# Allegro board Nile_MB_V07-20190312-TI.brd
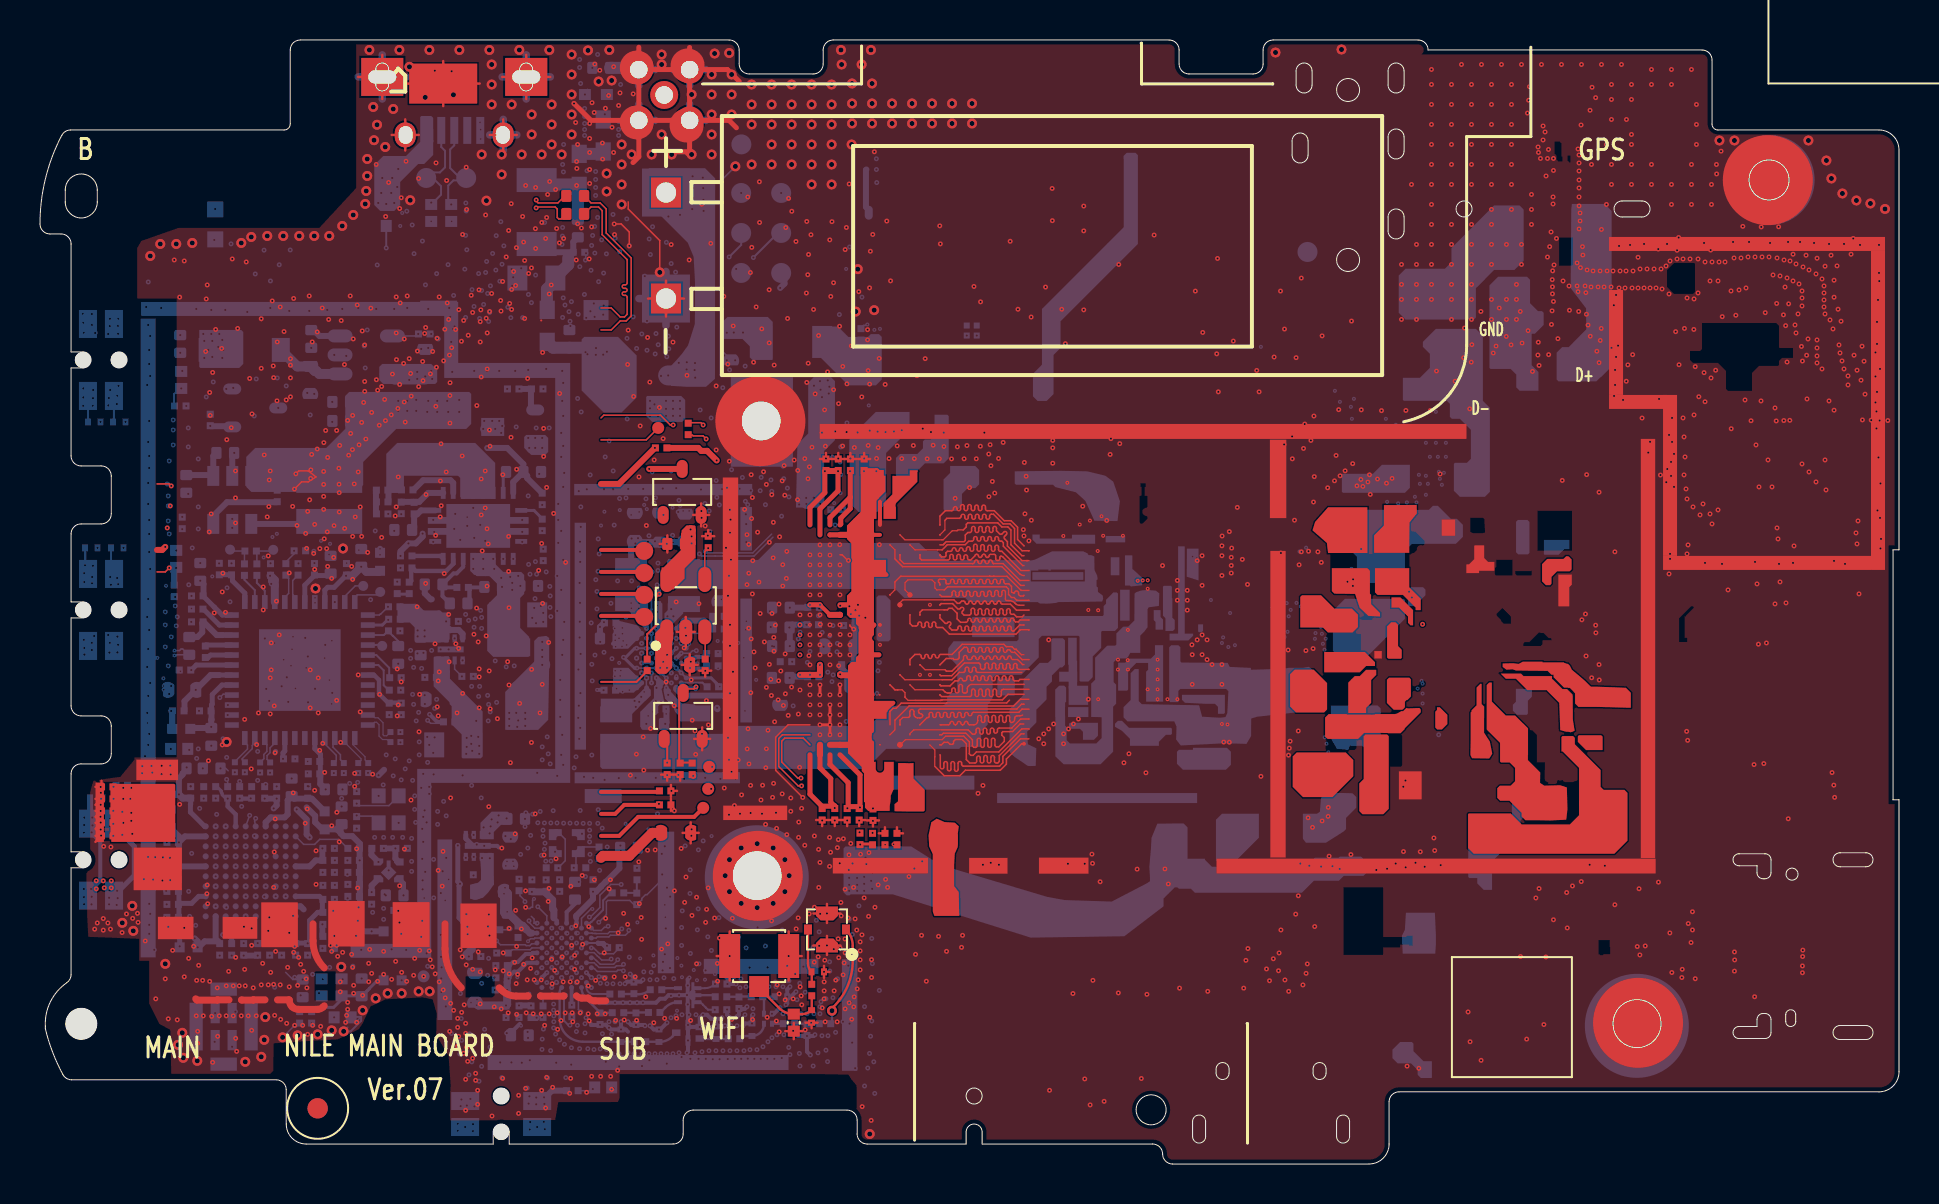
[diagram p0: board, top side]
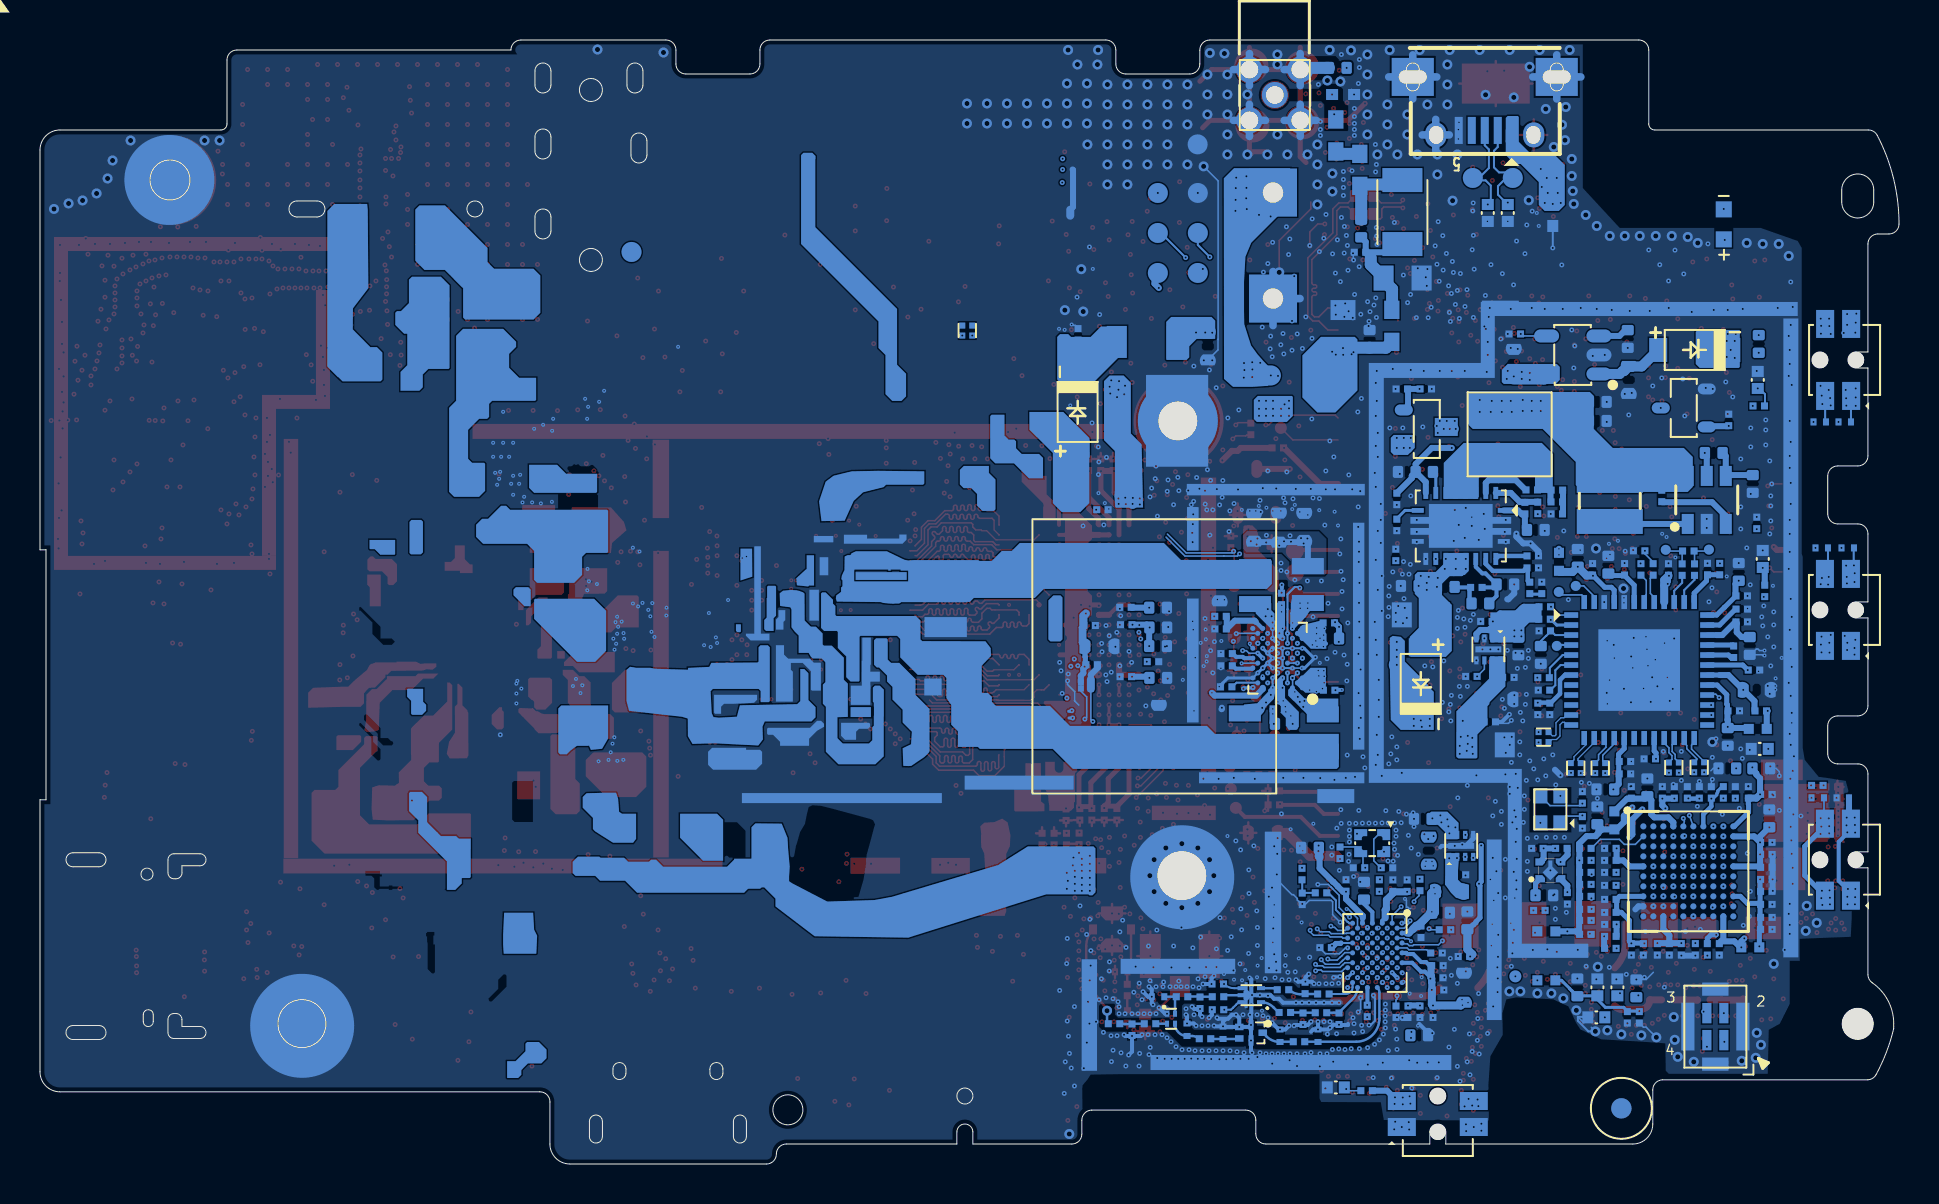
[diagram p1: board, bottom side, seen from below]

Outline 92.96 x 56.21 mm; copper layers: TOP, INNER LAYER 2, INNER LAYER 3, INNER LAYER 4, INNER LAYER 5, INNER LAYER 6, INNER LAYER 7, INNER LAYER 8, INNER LAYER 9, BOTTOM. Coordinates in mm from the lower left corner of the outline.

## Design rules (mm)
net group DIFFPAIR4: nets USB3_HS_CONN_DM_R USB3_HS_CONN_DP_R
net group DIFFPAIR5: nets USB3_HS_DET_DM USB3_HS_DET_DP
net group DIFFPAIR6: nets MIPI_DSI0_L0_M MIPI_DSI0_L0_P
net group DIFFPAIR7: nets MIPI_DSI0_CLK_M MIPI_DSI0_CLK_P
net group DIFFPAIR8: nets MIPI_DSI0_L1_M MIPI_DSI0_L1_P
net group DIFFPAIR18: nets USB_HUB2_DN USB_HUB2_DP
net group DIFFPAIR19: nets RIN0_M RIN0_P
net group DIFFPAIR20: nets N17038564 N17038587
net group DIFFPAIR21: nets N13800591 N13800619
net group DP_AUX: nets DP_AUX_M DP_AUX_P
net group EBI1EBI0_CLK_: nets EBI0_CLK_N EBI0_CLK_P
net group EBI1EBI0_DQS_0_: nets EBI0_DQS_0_N EBI0_DQS_0_P
net group EBI1EBI0_DQS_1_: nets EBI0_DQS_1_N EBI0_DQS_1_P
net group EBI1EBI1_CLK_: nets EBI1_CLK_N EBI1_CLK_P
net group EBI1EBI1_DQS_0_: nets EBI1_DQS_0_N EBI1_DQS_0_P
net group EBI1EBI1_DQS_1_: nets EBI1_DQS_1_N EBI1_DQS_1_P
net group IMP: nets CAM_MCLK0 SLEEP_CLK
net group IMP_50_OHM: nets SPMI_CLK SPMI_DATA
net group MIPI_CSI0_CLK_M: nets MIPI_CSI0_CLK_M MIPI_CSI0_CLK_M_R
net group MIPI_CSI0_CLK_P: nets MIPI_CSI0_CLK_P MIPI_CSI0_CLK_P_R
net group MIPI_CSI0_L0_DATA_M: nets MIPI_CSI0_L0_DATA_M MIPI_CSI0_L0_DATA_M_R
net group MIPI_CSI0_L0_DATA_P: nets MIPI_CSI0_L0_DATA_P MIPI_CSI0_L0_DATA_P_R
net group MIPI_CSI0_L1_DATA_M: nets MIPI_CSI0_L1_DATA_M MIPI_CSI0_L1_DATA_M_R
net group MIPI_CSI0_L1_DATA_P: nets MIPI_CSI0_L1_DATA_P MIPI_CSI0_L1_DATA_P_R
net group MIPI_CSI0_L2_DATA_M: nets MIPI_CSI0_L2_DATA_M MIPI_CSI0_L2_DATA_M_R
net group MIPI_CSI0_L2_DATA_P: nets MIPI_CSI0_L2_DATA_P MIPI_CSI0_L2_DATA_P_R
net group MIPI_CSI0_L3_DATA_M: nets MIPI_CSI0_L3_DATA_M MIPI_CSI0_L3_DATA_M_R
net group MIPI_CSI0_L3_DATA_P: nets MIPI_CSI0_L3_DATA_P MIPI_CSI0_L3_DATA_P_R
net group MIPI_CSI1_CLK: nets MIPI_CSI1_CLK_M MIPI_CSI1_CLK_P
net group MIPI_CSI1_L0: nets MIPI_CSI1_L0_DATA_M MIPI_CSI1_L0_DATA_P
net group MIPI_CSI1_L1: nets MIPI_CSI1_L1_DATA_M MIPI_CSI1_L1_DATA_P
net group MIPI_CSI1_L2: nets MIPI_CSI1_L2_DATA_M MIPI_CSI1_L2_DATA_P
net group MIPI_CSI1_L3: nets MIPI_CSI1_L3_DATA_M MIPI_CSI1_L3_DATA_P
net group SDC1_CLK: nets N16803139 SDC1_CLK
net group SDC1_RCLK: nets N16802968 SDC1_RCLK
net group SDC2_CLK: nets N13685743 SDC2_CLK
net group USB2_HS_D: nets USB2_HS_D_M USB2_HS_D_P
net group USB3_SBU: nets USB3_SBU1 USB3_SBU2
net group USB3_SS_RX0_CONN_M: nets USB3_SS_RX0_CONN_M USB3_SS_RX0_N
net group USB3_SS_RX0_CONN_P: nets USB3_SS_RX0_CONN_P USB3_SS_RX0_P
net group USB3_SS_RX1_CONN_M: nets USB3_SS_RX1_CONN_M USB3_SS_RX1_N
net group USB3_SS_RX1_CONN_P: nets USB3_SS_RX1_CONN_P USB3_SS_RX1_P
net group USB3_SS_TX0_CONN_M: nets USB3_SS_TX0_CONN_M USB3_SS_TX0_N
net group USB3_SS_TX0_CONN_P: nets USB3_SS_TX0_CONN_P USB3_SS_TX0_P
net group USB3_SS_TX1_CONN_M: nets USB3_SS_TX1_CONN_M USB3_SS_TX1_N
net group USB3_SS_TX1_CONN_P: nets USB3_SS_TX1_CONN_P USB3_SS_TX1_P
net group USB_HUB1: nets USB_HUB1_DN USB_HUB1_DP
net group DDR_EBI0_DQ0-7: nets EBI0_DQ0 EBI0_DQ1 EBI0_DQ2 EBI0_DQ3 EBI0_DQ4 EBI0_DQ5 EBI0_DQ6 EBI0_DQ7
net group DDR_EBI0_DQ8-15: nets EBI0_DQ8 EBI0_DQ9 EBI0_DQ10 EBI0_DQ11 EBI0_DQ12 EBI0_DQ13 EBI0_DQ14 EBI0_DQ15
net group DDR_EBI1_DQ0-7: nets EBI1_DQ0 EBI1_DQ1 EBI1_DQ2 EBI1_DQ3 EBI1_DQ4 EBI1_DQ5 EBI1_DQ6 EBI1_DQ7
net group DDR_EMI1_DQ8-15: nets EBI1_DQ8 EBI1_DQ9 EBI1_DQ10 EBI1_DQ11 EBI1_DQ12 EBI1_DQ13 EBI1_DQ14 EBI1_DQ15
net group PWR: nets VPH_PWR
net group SDC1: nets SDC1_DATA_0 SDC1_DATA_1 SDC1_DATA_2 SDC1_DATA_3 SDC1_DATA_4 SDC1_DATA_5 SDC1_DATA_6 SDC1_DATA_7
net group SDC1_EMMC: nets SDC1_CMD

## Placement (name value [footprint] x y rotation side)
B2  120R/1.3A  [FB0402H0_5]  17 30.12 90 bottom
B3  120R/1.3A  [FB0402H0_5]  7.06 21.76 180 bottom
B4  1000R/0.3A  [FB0402H0_5]  17.63 9.18 0 bottom
B9  BLM18HE152SZ1  [FB0603H0_8]  28.16 51.43 90 bottom
B30  120R/1.3A  [FB0402H0_5]  7.43 10.83 0 bottom
B32  120R/1.3A  [FB0402H0_5]  17.63 11.63 180 bottom
B33  120R/1.3A  [FB0402H0_5]  14.23 17.18 90 bottom
B34  BLM18HE152SZ1  [FB0603H0_8]  25.36 41.91 90 bottom
B35  BLM18HE152SZ1  [FB0603H0_8]  26.96 49.71 90 bottom
BTTN1  SKSCLBE010  [SW4-4_85X3_55H1_25]  23.06 2.5 180 bottom
BTTN3  SKSCLBE010  [SW4-4_85X3_55H1_25]  3.05 15.22 90 bottom
BTTN5  SKSCLBE010  [SW4-4_85X3_55H1_25]  3.04 40.21 90 bottom
BTTN6  SKSCLBE010  [SW4-4_85X3_55H1_25]  3.05 27.71 90 bottom
C9  1uF/6.3V_1  [SC0201]  39.74 17.49 270 top
C65  1uF/6.3V_1  [SC0201]  39.3 34.97 90 top
C113  33nF/10V_1  [SC0201]  10.22 29.72 90 bottom
C114  33nF/10V_1  [SC0201]  10.84 29.72 90 bottom
C115  1uF/25V_2  [SC0402]  19.03 25.88 270 bottom
C116  100nF/10V_1  [SC0201]  20.63 27.13 0 bottom
C118  1uF/6.3V_1  [SC0201]  37.3 25.12 180 bottom
C119  1uF/6.3V_1  [SC0201]  38.64 26.97 0 bottom
C122  1uF/6.3V_1  [SC0201]  39.11 17.49 270 top
C123  1uF/6.3V_1  [SC0201]  39.92 34.97 90 top
C124  2.2uF/10V_2  [SC0402]  37.04 26.83 180 bottom
C125  2.2uF/10V_2  [SC0402]  37.05 25.9 180 bottom
C126  100nF/10V_1  [SC0201]  38.66 24.37 0 bottom
C127  2.2uF/10V_2  [SC0402]  37.04 24.31 180 bottom
C128  100nF/10V_1  [SC0201]  38.68 27.84 0 bottom
C129  2.2uF/10V_2  [SC0402]  37.05 27.82 180 bottom
C131  1uF/6.3V_1  [SC0201]  40.97 17.49 270 top
C134  1uF/6.3V_1  [SC0201]  41.21 34.97 90 top
C138  1uF/6.3V_1  [SC0201]  40.53 34.97 90 top
C139  1uF/6.3V_1  [SC0201]  40.36 17.49 270 top
C142  1uF/6.3V_1  [SC0201]  40.37 24.97 180 bottom
C143  1uF/6.3V_1  [SC0201]  40.47 26.93 180 bottom
C144  1uF/6.3V_1  [SC0201]  39.83 32.72 180 bottom
C147  22uF/10V_3  [SC0603-CL10A226MP8NUNE]  31.01 31.82 90 bottom
C148  NC  [SC0603]  32.25 31.82 90 bottom
C151  1uF/6.3V_1  [SC0201]  41.65 17.47 270 top
C152  22uF/10V_3  [SC0603-CL10A226MP8NUNE]  39.98 25.89 180 bottom
C221  1uF/6.3V_1  [SC0201]  28.5 23.69 180 bottom
C223  10uF/6.3V_2  [SC0402]  28.44 26.28 180 bottom
C224  1uF/6.3V_1  [SC0201]  28.51 27.06 180 bottom
C225  NC  [SC0603]  29.74 31.86 90 bottom
C226  100nF/10V_1  [SC0201]  33.65 23.86 0 bottom
C227  1uF/6.3V_1  [SC0201]  30.88 28.26 90 bottom
C228  NC  [SC0603]  33.97 28.84 270 bottom
C229  1uF/6.3V_1  [SC0201]  33.63 25.52 0 bottom
C230  10uF/6.3V_2  [SC0402]  30.76 22.01 0 bottom
C231  1uF/6.3V_1  [SC0201]  31.01 22.76 0 bottom
C232  NC  [SC0603]  37.01 22.26 90 bottom
C255  10uF/6.3V_2  [SC0402]  22.9 12.57 180 bottom
C256  4.7uF/10V_2  [SC0402]  23.99 6.44 180 bottom
C257  1uF/6.3V_1  [SC0201]  26.59 7.66 270 bottom
C258  22uF/10V_3  [SC0603-CL10A226MP8NUNE]  21.75 8.82 90 bottom
C259  100pF/50V_1  [SC0201]  23.3 7.62 270 bottom
C260  10nF/10V_1  [SC0201]  24.6 13.92 90 bottom
C261  1uF/6.3V_1  [SC0201]  24.55 7.62 270 bottom
C262  4.7uF/10V_2  [SC0402]  29.45 15.82 0 bottom
C263  470nF/6.3V_1  [SC0201]  27.65 13.93 90 bottom
C264  10nF/10V_1  [SC0201]  23.08 9.92 180 bottom
C265  100nF/10V_1  [SC0201]  25.31 13.92 90 bottom
C266  10nF/10V_1  [SC0201]  23.95 7.62 270 bottom
C267  470nF/6.3V_1  [SC0201]  21.76 10.38 0 bottom
C268  10nF/10V_1  [SC0201]  23.09 9.31 180 bottom
C269  10uF/6.3V_2  [SC0402]  21.58 12.18 90 bottom
C270  10nF/10V_1  [SC0201]  28.67 10.82 0 bottom
C271  10nF/10V_1  [SC0201]  23.05 8.7 180 bottom
C272  10nF/10V_1  [SC0201]  23.9 11.62 270 bottom
C273  2.2uF/10V_2  [SC0402]  26.75 13.67 90 bottom
C274  4.7uF/10V_2  [SC0402]  23.81 17.26 0 bottom
C275  1uF/6.3V_1  [SC0201]  21.95 14.47 180 bottom
C277  8.2pF/50V_1  [SC0201]  25.6 14.82 180 bottom
C278  4.7pF/50V_1  [SC0201]  27 14.82 180 bottom
C279  22pF/50V_1  [SC0201]  28.9 13.56 0 bottom
C280  39pF/50V_1  [SC0201]  29.84 13.26 270 bottom
C281  33pF/50V_1  [SC0201]  34.05 7.72 0 bottom
C282  100pF/50V_1  [SC0201]  30.71 7.58 180 bottom
C283  33pF/50V_1  [SC0201]  34.07 9 0 bottom
C284  100pF/50V_1  [SC0201]  30.8 8.72 180 bottom
C285  NC  [SC0201]  29.7 8.81 90 bottom
C286  4.7pF/50V_1  [SC0201]  35.85 8.37 0 bottom
C287  10pF/50V_1  [SC0201]  30 6.12 0 bottom
C288  33pF/50V_1  [SC0201]  34.7 6.27 0 bottom
C309  10uF/16V_3  [SC0603]  19.26 40.06 90 bottom
C310  10uF/16V_3  [SC0603]  13.51 39.21 270 bottom
C358  10uF/16V_3  [SC0603]  7.11 23.71 180 bottom
C359  4.7uF/10V_2  [SC0402]  16.06 30.31 270 bottom
C360  10nF/10V_1  [SC0201]  15.32 29.74 90 bottom
C361  10nF/10V_1  [SC0201]  11.53 29.73 90 bottom
C363  33nF/10V_1  [SC0201]  12.29 29.73 90 bottom
C364  47nF/10V_1  [SC0201]  12.9 29.73 90 bottom
C365  4.7uF/10V_2  [SC0402]  8.01 29.61 270 bottom
C366  10nF/10V_1  [SC0201]  7.86 28.41 180 bottom
C367  10nF/10V_1  [SC0201]  7.25 24.7 180 bottom
C369  4.7uF/10V_2  [SC0402]  14.68 18.73 180 bottom
C370  10nF/10V_1  [SC0201]  13.7 19.51 180 bottom
C371  10nF/10V_1  [SC0201]  13.7 20.13 180 bottom
C373  10nF/10V_1  [SC0201]  13.72 29.74 90 bottom
C374  4.7uF/10V_2  [SC0402]  7.46 25.91 90 bottom
C375  4.7uF/10V_2  [SC0402]  14.53 29.97 270 bottom
C376  10nF/10V_1  [SC0201]  7.86 27.11 180 bottom
C377  4.7uF/10V_2  [SC0402]  17.91 25.46 90 bottom
C378  10nF/10V_1  [SC0201]  17.71 26.66 0 bottom
C379  4.7uF/10V_2  [SC0402]  8.58 19.78 180 bottom
C380  10nF/10V_1  [SC0201]  12.46 20.26 0 bottom
C381  10nF/10V_1  [SC0201]  17.46 22.76 270 bottom
C383  100nF/10V_1  [SC0201]  8.26 22.66 180 bottom
C384  10nF/10V_1  [SC0201]  18.06 22.76 270 bottom
C394  100nF/10V_1  [SC0201]  13.58 7.33 270 bottom
C395  NC  [SC0402]  16.08 8.83 90 bottom
C416  12pF/50V_1  [SC0201]  15.83 18.33 90 bottom
C417  12pF/50V_1  [SC0201]  15.83 17.08 270 bottom
C418  22uF/10V_3  [SC0603-CL10A226MP8NUNE]  20.03 23.23 180 bottom
C424  100nF/10V_1  [SC0201]  11.23 18.58 270 bottom
C437  100nF/10V_1  [SC0201]  32.01 19.76 90 top
C438  100nF/50V_2  [SC0402]  26.47 41.26 90 bottom
C442  NC  [SC0201]  27.95 15.57 90 bottom
C446  1nF/50V_1  [SC0201]  41.05 41.49 90 bottom
C452  10uF/6.3V_2  [SC0402]  6.48 17.28 90 bottom
C453  10uF/6.3V_2  [SC0402]  8.56 21.36 270 bottom
C556  NC  [SC0201]  38.35 6.72 270 bottom
C4607  10uF/16V_3  [SC0603]  31.81 24.96 0 top
C4608  1uF/25V_2  [SC0402]  31.81 31.01 180 top
C6216  47uF/6.3V_5  [SC0805]  20.66 20.96 180 bottom
C6217  100nF/10V_1  [SC0201]  3.36 18.86 0 top
C6223  100nF/10V_1  [SC0201]  11.83 18.58 270 bottom
C6224  100nF/10V_1  [SC0201]  14.43 13.93 180 bottom
C6225  100nF/10V_1  [SC0201]  9.38 18.58 270 bottom
C6231  100nF/10V_1  [SC0201]  6.63 11.73 0 bottom
C6233  10uF/25V_5  [SC0805]  24.82 44.3 180 bottom
C6234  100nF/10V_1  [SC0201]  19.53 24.33 180 bottom
C6270  10uF/6.3V_2  [SC0402]  15.06 38.11 180 bottom
C6271  100nF/10V_1  [SC0201]  23.66 38.76 180 bottom
C6272  100nF/10V_1  [SC0201]  25.11 33.26 270 bottom
C6273  33pF/50V_1  [SC0201]  12.98 7.33 90 bottom
C6274  100nF/10V_1  [SC0201]  20.46 22.11 0 bottom
C6277  GPL2R7156M1232-B05  [CAP2-5_3-33X13H13]  31.3 45.93 270 top
C6278  2.2uF/10V_2  [SC0402]  17.73 13.43 180 bottom
C6283  1uF/50V_3  [SC0603]  34.56 40.89 90 bottom
C6288  2.7pF/50V_1  [SC0201]  42.85 16.25 90 top
C6289  2.7pF/50V_1  [SC0201]  42.25 16.25 90 top
C6299  10uF/6.3V_2  [SC0402]  24.61 34.61 0 bottom
C6300  4.7uF/10V_2  [SC0402]  15.06 37.16 180 bottom
C6301  100nF/50V_2  [SC0402]  22.86 34.61 180 bottom
C6302  4.7uF/10V_2  [SC0402]  18.16 31.71 0 bottom
C6303  1uF/25V_2  [SC0402]  24.46 28.91 0 bottom
C6305  47uF/6.3V_5  [SC0805]  23.91 27.46 0 bottom
C6306  47nF/10V_1  [SC0201]  25.11 31.96 90 bottom
C6307  10nF/10V_1  [SC0201]  17.86 28.81 270 bottom
C6308  100pF/50V_1  [SC0201]  18.31 29.81 0 bottom
C6309  NC  [SC0201]  17.11 32.51 0 bottom
C6310  NC  [SC0201]  21.13 28.83 180 bottom
C6329  100pF/50V_1  [SC0201]  34.05 8.37 180 bottom
C6361  68pF/50V_1  [SC0201]  3.36 18.26 0 top
C6362  33pF/50V_1  [SC0201]  3.36 17.06 0 top
C6363  10nF/10V_1  [SC0201]  3.36 17.66 0 top
C6364  10pF/50V_1  [SC0201]  3.36 16.41 0 top
C6365  100nF/10V_1  [SC0201]  31.26 17.96 180 top
C6366  22uF/10V_3  [SC0603-CL10A226MP8NUNE]  31.81 16.56 0 top
C6367  33pF/50V_1  [SC0201]  7.11 32.06 270 bottom
C6368  1uF/6.3V_1  [SC0201]  16.58 13.28 270 bottom
C6369  100nF/10V_1  [SC0201]  18.08 15.78 180 bottom
C6370  10uF/6.3V_2  [SC0402]  15.08 17.43 90 bottom
C6371  10uF/6.3V_2  [SC0402]  6.88 19.78 180 bottom
C6376  100nF/10V_1  [SC0201]  13.38 18.58 270 bottom
C6379  10nF/10V_1  [SC0201]  7.53 18.58 90 bottom
C6380  1nF/50V_1  [SC0201]  6.63 14.23 180 bottom
C6381  10nF/10V_1  [SC0201]  6.63 13.63 180 bottom
C6383  10nF/10V_1  [SC0201]  6.63 18.48 180 bottom
C6384  1nF/50V_1  [SC0201]  14.43 12.58 0 bottom
C6385  10nF/10V_1  [SC0201]  14.43 13.23 0 bottom
C6386  1nF/50V_1  [SC0201]  6.63 12.33 180 bottom
C6387  10nF/10V_1  [SC0201]  6.63 12.98 180 bottom
C6388  1nF/50V_1  [SC0201]  12.78 10.73 270 bottom
C6389  10nF/10V_1  [SC0201]  13.38 10.73 270 bottom
C6393  100nF/10V_1  [SC0201]  6.63 16.08 0 bottom
C6394  10nF/10V_1  [SC0201]  11.48 10.73 270 bottom
C6395  100nF/10V_1  [SC0201]  12.08 10.73 90 bottom
C6396  100nF/10V_1  [SC0201]  9.98 18.58 270 bottom
C6397  100nF/10V_1  [SC0201]  10.58 18.58 270 bottom
C6398  100nF/10V_1  [SC0201]  6.63 15.48 0 bottom
C6399  100nF/10V_1  [SC0201]  14.43 15.18 180 bottom
C6400  100nF/10V_1  [SC0201]  6.63 14.83 0 bottom
C6401  100nF/10V_1  [SC0201]  8.98 10.73 90 bottom
C6402  100nF/10V_1  [SC0201]  10.88 10.73 90 bottom
C6403  100nF/10V_1  [SC0201]  14.43 15.78 180 bottom
C6404  10uF/6.3V_2  [SC0402]  12.58 18.83 90 bottom
C6405  10nF/50V_1  [SC0201]  26.95 45.59 0 bottom
C6406  10uF/25V_5  [SC0805]  27.8 41.75 90 bottom
CN3  SAR180001  [TP1-5_9X2H3_7]  20.36 54.03 0 top
CON2  MMCX-33102  [RAJ5-3_5X3_5H4]  31.21 53.46 0 bottom
D31  ESD5311N  [DFN1006-2L-H0_5]  15.08 8.83 90 bottom
D32  ESD5311N  [DFN1006-2L-H0_5]  15.13 7.33 0 bottom
D33  ESD5311N  [DFN1006-2L-H0_5]  14.08 8.83 90 bottom
D37  RS0402-12V0R8S  [ESD0402H0_6]  17.31 47.46 270 bottom
D38  ESD5311N  [DFN1006-2L-H0_5]  19.56 47.56 270 bottom
D39  ESD5311N  [DFN1006-2L-H0_5]  20.56 47.56 270 bottom
D48  RS0402-12V0R8S  [ESD0402H0_6]  27.8 53.48 180 bottom
D3600  LMBR140FT1G  [SOD123H1_4]  10.21 40.71 180 bottom
D3707  LMBR140FT1G  [SOD123H1_4]  41.07 37.61 90 bottom
D3829  ESD5311N  [DFN1006-2L-H0_5]  28.16 3.83 0 bottom
D3845  ESD5311N  [DFN1006-2L-H0_5]  6.96 20.76 0 bottom
D3847  ESD5311N  [DFN1006-2L-H0_5]  7.06 39.21 90 bottom
D3848  ESD5311N  [DFN1006-2L-H0_5]  6.81 30.26 90 bottom
D3853  LMBR140FT1G  [SOD123H1_4]  23.91 24.01 270 bottom
D3865  ESD5311N  [DFN1006-2L-H0_5]  37.69 7.07 270 top
F2818  90R/0.13A  [CMC4-0_87X0_67H0_5]  14.94 19.8 180 bottom
F2819  90R/0.13A  [CMC4-0_87X0_67H0_5]  9.99 19.84 180 bottom
F2820  90R/0.13A  [CMC4-0_87X0_67H0_5]  17.77 21.35 270 bottom
F2821  90R/0.13A  [CMC4-0_87X0_67H0_5]  11.26 19.83 180 bottom
F2822  90R/0.13A  [CMC4-0_87X0_67H0_5]  16.16 19.8 180 bottom
F2824  90R/0.13A  [CMC4-0_87X0_67H0_5]  46.59 41.68 0 bottom
FL1  DPX105950DT-6112A1  [DUP4-1X0_5H0_4]  36.4 7.27 270 bottom
FL2  SAFEA2G45MB0F0A  [SAW5-1_35X1_05H0_5]  32.4 6.57 0 bottom
G15  @SG-L5  [SCP0_15]  27.86 23.71 0 bottom
G16  @SG-L5  [SCP0_15]  28.01 26.11 90 bottom
G17  @SG-L5  [SCP0_15]  31.26 22.01 90 bottom
G18  @SG-L5  [SCP0_15]  30.86 28.81 270 bottom
HOLE1  SMT NUT  [HOLE4_0D2_4]  35.86 14.42 0 top
HOLE3  SMT NUT  [H4_0D1_9]  36.06 37.16 180 bottom
J3  MM8030-2610RK0/RF  [RF4-MM8030H1]  39.35 11.73 270 top
J4  U.FL-R-SMT-1(60)  [RF3-SQ2_6H1_25-UFL-R-SMT-1]  35.96 10.4 0 top
L8  0.47uH  [SL2016-1_85H1_2]  28.81 21.56 270 bottom
L9  0.47uH  [SL2016-1_85H1_2]  29.56 28.98 90 bottom
L10  0.47uH  [SL2016-1_85H1_2]  32.2 28.93 90 bottom
L11  0.47uH  [SL2016-1_85H1_2]  32.71 21.61 270 bottom
L20  NC  [SL0201H0_3]  38.89 9.61 180 top
L22  NC  [SL0201H0_3]  38.58 7.38 90 top
L25  1.5nH  [SL0201H0_3]  37.05 8.37 180 bottom
L26  NC  [SL0201H0_3]  29.05 6.42 270 bottom
L27  6.8nH  [SL0201H0_3]  30.95 6.42 90 bottom
L28  6.2nH  [SL0201H0_3]  33.8 6.57 90 bottom
L29  NC  [SL0201H0_3]  35.6 6.72 270 bottom
L36  10uH  [SL3225H2_5]  24.83 47.6 90 bottom
L3703  6.8uH  [SL3030-2_05H0_9]  14.46 33.16 270 bottom
L3704  NC  [SC0201]  34.95 8.06 90 bottom
L3709  1.0uH  [SL4020-1_9H2]  19.46 36.46 270 bottom
L3710  100nH  [SL0201H0_3]  4.06 18.31 180 bottom
L3711  100nH  [SL0201H0_3]  2.81 18.31 180 bottom
L3712  100nH  [SL0201H0_3]  3.96 37.11 180 bottom
L3713  100nH  [SL0201H0_3]  2.71 37.11 180 bottom
L3714  100nH  [SL0201H0_3]  3.86 30.81 180 bottom
L3715  100nH  [SL0201H0_3]  2.56 30.81 180 bottom
LED4400  GREEN  [LED0603X2H0_35]  8.76 46.99 90 bottom
MK1  MARK  [MARK-TOP]  13.88 2.78 0 top
MK4  MARK  [MARK-TOP]  13.88 2.78 180 bottom
NOREF  -  []  -5.61 51.85 0 top
NOREF#2  -  []  97.47 51.58 180 bottom
PS3  0.12A  [F3418H0_7]  37.61 41.11 180 bottom
Q8  LBSS138LT1G  [SOT23H1_1]  10.76 37.81 90 bottom
Q2710  WPM3012-3/TR  [SOT23H1_1]  23.61 36.76 270 bottom
Q2711  LBSS138LT1G  [SOT23H1_1]  32.11 33.61 0 top
Q2712  LBSS138LT1G  [SOT23H1_1]  32.16 22.41 0 top
R1  100/F_1  [SR0201]  10.53 30.65 0 bottom
R7  10K_1  [SR0201]  21.38 24.38 0 bottom
R20  2.2K_1  [SR0201]  17.71 27.87 0 bottom
R21  2.2K_1  [SR0201]  17.72 27.25 0 bottom
R60  NC(short)  [SCP0_3]  40.91 24.08 270 bottom
R61  NC(short)  [SCP0_3]  40.41 24.07 270 bottom
R87  NC  [SR0201]  33.93 27.39 180 bottom
R88  NC  [SR0201]  33.93 26.76 0 bottom
R89  10K_1  [SR0201]  33.63 24.91 180 bottom
R100  0_3  [SR0603]  23.51 15.67 270 bottom
R102  0_3  [SR0603]  22.5 13.62 0 bottom
R105  22/F_1  [SR0201]  23.96 13.95 90 bottom
R106  51K_1  [SR0201]  23.13 10.55 180 bottom
R110  0_1  [SR0201]  25.99 13.93 270 bottom
R115  0_1  [SR0201]  29.85 14.5 90 bottom
R116  0_1  [SR0201]  28.9 7.57 180 bottom
R117  0.2pF/25V_1  [SR0201]  29.8 7.27 270 bottom
R118  NC  [SR0201]  28 7.27 270 bottom
R119  0_1  [SR0201]  28.79 8.5 180 bottom
R120  0_1  [SR0201]  39.25 7.02 0 bottom
R121  0_1  [SR0201]  37.45 7.02 0 bottom
R122  0_1  [SR0201]  38.59 8.7 270 top
R124  NC  [SR0201]  25.15 7.62 270 bottom
R147  10K_1  [SR0201]  19.21 41.51 0 bottom
R194  0_1  [SR0201]  17.77 24.32 180 bottom
R195  10K_1  [SR0201]  6.91 22.66 0 bottom
R196  78.7K/F_1  [SR0201]  8.97 29.75 270 bottom
R198  97.6K/F_1  [SR0201]  9.58 29.75 90 bottom
R199  10K_1  [SR0201]  7.86 27.75 180 bottom
R200  10K_1  [SR0201]  17.75 23.7 0 bottom
R201  NC  [SR0201]  12.99 30.66 0 bottom
R231  0_2  [SR0402]  13.13 8.78 270 bottom
R253  1.2K/F_1  [SR0201]  22.7 11.72 0 bottom
R284  1K_1  [SR0201]  7.01 37.91 0 bottom
R286  1K_1  [SR0201]  4.08 18.93 180 bottom
R288  1K_1  [SR0201]  26.62 3.67 180 bottom
R289  1K_1  [SR0201]  6.71 28.66 270 bottom
R413  22K/F_2  [SR0402]  13.56 41.26 270 bottom
R479  10K_1  [SR0201]  15.68 11.48 0 bottom
R4647  10K_1  [SR0201]  33.41 31.11 90 top
R4648  10K/F_1  [SR0201]  33.26 24.96 270 top
R4656  240/F_1  [SR0201]  41.63 16.25 90 top
R4657  240/F_1  [SR0201]  41 16.26 90 top
R6285  10m/F_3  [SR0603]  31.41 38.76 90 bottom
R6362  820_2  [SR0402]  7.01 41.01 90 bottom
R6536  0_1  [SR0201]  30.36 24.96 90 top
R6537  10K_1  [SR0201]  8.51 37.21 270 bottom
R6546  4.02K/F_2  [SR0402]  26.89 46.78 90 bottom
R6547  49.9/F_2  [SR0402]  28.06 54.81 180 bottom
R6548  NC  [SR0201]  8.27 25.62 90 bottom
R6578  10K_1  [SR0201]  11.86 33.41 270 bottom
R6579  100K_1  [SR0201]  24.86 38.76 180 bottom
R6580  100K/F_2  [SR0402]  7.31 34.01 270 bottom
R6581  1M/F_2  [SR0402]  9.26 35.56 180 bottom
R6626  10K_1  [SR0201]  18.71 32.8 90 bottom
R6627  NC  [SR0201]  25.16 30.46 270 bottom
R6628  301K/F_1  [SR0201]  18.36 33.71 0 bottom
R6630  91K/F_2  [SR0402]  20.93 28.03 180 bottom
R6631  42.2K/F_2  [SR0402]  19.68 28.98 180 bottom
R6632  95.3K/F_1  [SR0201]  18.31 30.41 0 bottom
R6633  3.92K/F_1  [SR0201]  18.46 28.81 90 bottom
R6634  NC  [SR0201]  17.11 33.11 180 bottom
R6635  NC  [SR0201]  17.11 33.7 180 bottom
R6636  49.9/F_2  [SR0402]  22.66 28.86 180 bottom
R6642  NC  [SR0201]  18.06 32.81 90 bottom
R6653  0_2  [SR0402]  26.76 47.51 0 top
R6654  0_2  [SR0402]  26.76 48.41 0 top
R6655  10K_1  [SR0201]  31.36 19.76 90 top
R6656  NC  [SR0201]  32.61 19.76 90 top
R6657  0_1  [SR0201]  31.26 18.66 180 top
R6658  NC  [SR0201]  31.06 35.81 0 top
R6663  100K_1  [SR0201]  32.41 36.76 90 top
R6671  10K_1  [SR0201]  17.98 12.68 180 bottom
R6672  10K_1  [SR0201]  14.43 11.38 180 bottom
R6673  10K_1  [SR0201]  14.43 11.98 180 bottom
R6676  10K_1  [SR0201]  15.68 14.58 0 bottom
R6678  0_1  [SR0201]  14.43 10.78 180 bottom
R6679  10K_1  [SR0201]  15.68 13.38 180 bottom
R6680  10K_1  [SR0201]  15.68 15.18 180 bottom
R6681  6.04K/F_1  [SR0201]  14.43 14.58 180 bottom
R6682  200/F_1  [SR0201]  10.18 10.73 90 bottom
R6683  10K_1  [SR0201]  15.68 13.98 180 bottom
R6684  10K_1  [SR0201]  15.68 12.18 180 bottom
R6685  NC  [SR0201]  16.88 15.78 0 bottom
R6686  10K_1  [SR0201]  15.68 12.73 0 bottom
R6687  10K_1  [SR0201]  9.58 10.73 270 bottom
R6688  10K_1  [SR0201]  8.18 18.58 90 bottom
R6689  10K_1  [SR0201]  15.68 15.78 0 bottom
R6690  10K_1  [SR0201]  8.78 18.58 90 bottom
REF  val  [unnamed#2]  2.06 7.01 180 bottom
SH2  NILE-WIFI-shd-frame  [NILE-WIFI-SHD]  30.36 11.7 180 bottom
SH3  nile-PM8005-shd  [NILE-PM8005-SHD]  31.17 26.55 180 bottom
SH5  nile-power-shd  [NILE-POWER-SHD]  15.73 26.78 180 bottom
TP2  0.5mm  [TP0_5]  9.5 30.72 180 bottom
TP6  0.5mm  [TP0_5]  11.66 30.71 180 bottom
TP25  0.5mm  [TP0_5]  17.11 25.91 180 bottom
TP26  0.5mm  [TP0_5]  16.16 28.91 180 bottom
TP27  0.5mm  [TP0_5]  17.01 28.61 180 bottom
TP68  1.0mm  [TP1_0]  17.31 49.31 180 bottom
TP69  1.0mm  [TP1_0]  19.31 49.31 180 bottom
TP70  1.0mm  [TP1_0]  21.31 49.31 180 bottom
TP71  1.0mm  [TP1_0]  35.07 50.99 180 bottom
TP78  1.0mm  [TP1_0]  37.06 48.56 270 bottom
TP79  1.0mm  [TP1_0]  37.06 44.56 270 bottom
TP80  1.0mm  [TP1_0]  37.06 46.56 270 bottom
TP81  1.0mm  [TP1_0]  35.06 46.56 270 bottom
TP82  1.0mm  [TP1_0]  35.06 44.56 270 bottom
TP83  1.0mm  [TP1_0]  35.06 48.56 270 bottom
TP97  0.6mm  [TP0_6]  30.91 36.81 0 top
TP98  0.6mm  [TP0_6]  33.16 17.81 0 top
TP100  0.6mm  [TP0_6]  33.46 19.86 0 top
TP101  0.6mm  [TP0_6]  33.41 18.76 0 top
TP102  0.9mm  [TP0_9]  30.21 27.36 0 top
TP103  0.9mm  [TP0_9]  30.21 28.46 0 top
TP104  0.9mm  [TP0_9]  30.21 29.56 0 top
TP105  0.9mm  [TP0_9]  30.21 30.66 0 top
TP106  0.6mm  [TP0_6]  19.18 9.38 270 bottom
TP107  2.0mm  [TP2_0]  28.73 38.68 180 bottom
U2  RP115L181D-E2  [DFN8-0_4-1_6X1_2H0_4-P]  20.53 25.73 0 bottom
U11  PM8005  [BGA72-0_35-3_44X2_82H0_53]  31.08 25.3 90 bottom
U18  WCN3980  [BGA82-0_495-3_79X3_07H0_55]  26.21 10.55 0 bottom
U19  WL2817DA33-8/TR  [DFN8-0_4-1_6X1_2H0_4-P]  21.89 15.91 180 bottom
U22  SKY13351-378LF  [RF6-0_35-SQ1_0H1_0]  32.39 8.44 0 bottom
U33  DS90UB954  [VQFN48-0_5-7X7H1]  12.99 24.7 180 bottom
U35  MSM261D4030H1CPM  [NSM0411DT-BL-H1_1]  9.18 6.87 180 bottom
U3702  SY6280AAC  [SOT23-5H1_4]  32.29 27.92 0 top
U3704  SY6280AAC  [SOT23-5H1_4]  16.31 40.46 90 bottom
U3708  WL2831D12-4/TR  [DFN1212-4-SQ1_2H0_4]  17.43 14.68 180 bottom
U4619  TLV61220DBV  [SOT23-6H1_4]  9.61 33.21 180 bottom
U6834  TPS61088RHLR  [VQFN20-0_5-4_5X3_5H1_0]  21.91 31.91 270 bottom
U6838  CYUSB3312-BVXI  [BGA100-0_5-6X6H1]  10.53 14.63 180 bottom
USB1  211-200501-113  [USB5-7_5X5_3H2_7]  20.72 51.46 0 bottom
Y1  38.4MHZ  [CRY4-1_6X1_2H0_65]  26.34 16.05 0 bottom
Y2  26MHz  [CRY4-2016]  17.43 17.73 90 bottom

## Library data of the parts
B2 B3 B30 B32 B33 = L_BEAD
B4 = L_Bead
B9 B34 B35 L20 L22 L25-L29 L3710-L3715 = L_FI
BTTN1 BTTN3 BTTN5 BTTN6 = CON_SW_4P_SKSCLBE010
C9 C65 C113-C116 C118 C119 C122-C129 C131 C134 C138 C139 C142-C144 C147 C148 C151 C152 C221 C223-C232 C255-C275 C277-C285 C287 C288 C309 C310 C358-C361 C363-C367 C369-C371 C373-C381 C383 C384 C394 C395 C416-C418 C424 C437 C438 C442 C446 C452 C453 C556 C4607 C4608 C6216 C6217 C6223-C6225 C6231 C6233 C6234 C6270-C6274 C6278 C6283 C6288 C6289 C6299-C6303 C6305-C6310 C6329 C6361-C6371 C6376 C6379-C6381 C6383-C6389 C6393-C6406 L3704 = CAP
C286 = CAP_RF
C6277 = GPL2R7156M1232
CN3 = CON_818011226: User Part Number: PART
CON2 = CON_RF_5P_MMCX33102
D31-D33 D37-D39 D48 D3829 D3845 D3847 D3848 D3865 = DIODE_TVS
D3600 D3707 D3853 = DIODE_SCHOTTKY_D
F2818-F2822 F2824 = L_CC_EXC14CE900U: signal model: L_CC_EXC14CE900U_CMC4-0_87X0_67_90R/0.13A
FL1 = IC_DPX105950DT-6112A1
FL2 = IC_SAFEA2G45MB0F0A
G15-G18 = SG
HOLE1 HOLE3 = T_POINT-0.8: Tolerance: TOL
J3 = CON_RF_4P_MM8030
J4 = UFL-R-SMT-1
L8-L11 L36 L3703 L3709 = L_PI
LED4400 = DIODE_LED_S
MK1 MK4 = MARK
PS3 = FUSE_POLYSWITCH
Q8 Q2711 Q2712 = MOSFET_N
Q2710 = MOSFET_P_3P
R1 R7 R20 R21 R60 R61 R87-R89 R100 R102 R105 R106 R110 R115-R122 R124 R147 R194-R196 R198-R201 R231 R253 R284 R286 R288 R289 R413 R479 R4647 R4648 R4656 R4657 R6285 R6362 R6536 R6537 R6546-R6548 R6578-R6581 R6626-R6628 R6630-R6636 R6642 R6653-R6658 R6663 R6671-R6673 R6676 R6678-R6690 = RES
SH2 SH3 SH5 = XM-217-XC-001-CL_0
TP2 TP6 TP25-TP27 TP68-TP71 TP78-TP83 TP97 TP98 TP100-TP107 = TP
U2 = IC_RP115L281B-E2
U11 = PM8005
U18 = WCN3980
U19 = IC_WL2817DA33
U22 = IC_SKY13351-378LF
U33 = IC_DS90UB954-Q1
U35 = IC_NSM0411DT-BL_0
U3702 U3704 = IC_SY6280
U3708 = IC_WL2831D
U4619 = TLV61220DBV
U6834 = TPS61088RHLR
U6838 = CYUSB3312-BVXI
USB1 = CON_USB_5P
Y1 = CRYSTAL_38.4M_CT1612DB38400C0FL
Y2 = CRYSTAL_38.4M_8Y384

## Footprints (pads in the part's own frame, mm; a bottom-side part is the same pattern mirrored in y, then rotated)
BGA72-0_35-3_44X2_82H0_53
  round 0.25 smd: 1(-1.485,-1.238) 2(-1.485,-0.742) 3(-1.485,-0.248) 4(-1.485,0.248) 5(-1.485,0.742) 6(-1.485,1.238) 7(-1.238,-0.99) 8(-1.238,-0.495) 9(-1.238,0) 10(-1.238,0.495) 11(-1.238,0.99) 12(-0.99,-1.238) 13(-0.99,-0.742) 14(-0.99,-0.248) 15(-0.99,0.248) 16(-0.99,0.742) 17(-0.99,1.238) 18(-0.742,-0.99) 19(-0.742,-0.495) 20(-0.742,0) 21(-0.742,0.495) 22(-0.742,0.99) 23(-0.495,-1.238) 24(-0.495,-0.742) 25(-0.495,-0.248) 26(-0.495,0.248) 27(-0.495,0.742) 28(-0.495,1.238) 29(-0.248,-0.99) 30(-0.248,-0.495) 31(-0.248,0) 32(-0.248,0.495) 33(-0.248,0.99) 34(0,-1.238) 35(0,-0.742) 36(0,-0.248) 37(0,0.248) 38(0,0.742) 39(0,1.238) 40(0.248,-0.99) 41(0.248,-0.495) 42(0.248,0) 43(0.248,0.495) 44(0.248,0.99) 45(0.495,-1.238) 46(0.495,-0.742) 47(0.495,-0.248) 48(0.495,0.248) 49(0.495,0.742) 50(0.495,1.238) 51(0.742,-0.99) 52(0.742,-0.495) 53(0.742,0) 54(0.742,0.495) 55(0.742,0.99) 56(0.99,-1.238) 57(0.99,-0.742) 58(0.99,-0.248) 59(0.99,0.248) 60(0.99,0.742) 61(0.99,1.238) 62(1.238,-0.99) 63(1.238,-0.495) 64(1.238,0) 65(1.238,0.495) 66(1.238,0.99) 67(1.485,-1.238) 68(1.485,-0.742) 69(1.485,-0.248) 70(1.485,0.248) 71(1.485,0.742) 72(1.485,1.238)
BGA82-0_495-3_79X3_07H0_55
  round 0.25 smd: 1(-1.357,-1.49) 2(-1.357,-0.995) 3(-1.357,-0.5) 4(-1.357,-0.005) 5(-1.357,0.49) 6(-1.357,0.985) 7(-1.357,1.48) 8(-1.109,-1.242) 9(-1.109,-0.747) 10(-1.109,-0.252) 11(-1.109,0.243) 12(-1.109,0.738) 13(-1.109,1.233) 14(-1.109,1.728) 15(-0.862,-1.49) 16(-0.862,-0.995) 17(-0.862,-0.5) 18(-0.862,-0.005) 19(-0.862,0.49) 20(-0.862,0.985) 21(-0.862,1.48) 22(-0.614,-1.242) 23(-0.614,-0.747) 24(-0.614,-0.252) 25(-0.614,0.243) 26(-0.614,0.738) 27(-0.614,1.233) 28(-0.614,1.728) 29(-0.367,-1.49) 30(-0.367,-0.995) 31(-0.367,-0.5) 32(-0.367,-0.005) 33(-0.367,0.49) 34(-0.367,0.985) 35(-0.367,1.48) 36(-0.119,-1.242) 37(-0.119,-0.747) 38(-0.119,-0.252) 39(-0.119,0.243) 40(-0.119,0.738) 41(-0.119,1.233) 42(-0.119,1.728) 43(0.128,-1.49) 44(0.128,-0.995) 45(0.128,-0.5) 46(0.128,-0.005) 47(0.128,0.49) 48(0.128,0.985) 49(0.376,-1.242) 50(0.376,-0.747) 51(0.376,-0.252) 52(0.376,0.243) 53(0.376,0.738) 54(0.376,1.233) 55(0.376,1.728) 56(0.623,-1.49) 57(0.623,-0.995) 58(0.623,-0.5) 59(0.623,-0.005) 60(0.623,0.49) 61(0.623,0.985) 62(0.623,1.48) 63(0.871,-1.242) 64(0.871,-0.747) 65(0.871,-0.252) 66(0.871,0.738) 67(0.871,1.233) 68(0.871,1.728) 69(1.118,-1.49) 70(1.118,-0.995) 71(1.118,-0.5) 72(1.118,-0.005) 73(1.118,0.49) 74(1.118,0.985) 75(1.118,1.48) 76(1.366,-1.242) 77(1.366,-0.747) 78(1.366,-0.252) 79(1.366,0.243) 80(1.366,0.738) 81(1.366,1.233) 82(1.366,1.728)
BGA100-0_5-6X6H1
  round 0.305 smd: A1(-2.25,2.25) A2(-1.75,2.25) A3(-1.25,2.25) A4(-0.75,2.25) A5(-0.25,2.25) A6(0.25,2.25) A7(0.75,2.25) A8(1.25,2.25) A9(1.75,2.25) A10(2.25,2.25) B1(-2.25,1.75) B2(-1.75,1.75) B3(-1.25,1.75) B4(-0.75,1.75) B5(-0.25,1.75) B6(0.25,1.75) B7(0.75,1.75) B8(1.25,1.75) B9(1.75,1.75) B10(2.25,1.75) C1(-2.25,1.25) C2(-1.75,1.25) C3(-1.25,1.25) C4(-0.75,1.25) C5(-0.25,1.25) C6(0.25,1.25) C7(0.75,1.25) C8(1.25,1.25) C9(1.75,1.25) C10(2.25,1.25) D1(-2.25,0.75) D2(-1.75,0.75) D3(-1.25,0.75) D4(-0.75,0.75) D5(-0.25,0.75) D6(0.25,0.75) D7(0.75,0.75) D8(1.25,0.75) D9(1.75,0.75) D10(2.25,0.75) E1(-2.25,0.25) E2(-1.75,0.25) E3(-1.25,0.25) E4(-0.75,0.25) E5(-0.25,0.25) E6(0.25,0.25) E7(0.75,0.25) E8(1.25,0.25) E9(1.75,0.25) E10(2.25,0.25) F1(-2.25,-0.25) F2(-1.75,-0.25) F3(-1.25,-0.25) F4(-0.75,-0.25) F5(-0.25,-0.25) F6(0.25,-0.25) F7(0.75,-0.25) F8(1.25,-0.25) F9(1.75,-0.25) F10(2.25,-0.25) G1(-2.25,-0.75) G2(-1.75,-0.75) G3(-1.25,-0.75) G4(-0.75,-0.75) G5(-0.25,-0.75) G6(0.25,-0.75) G7(0.75,-0.75) G8(1.25,-0.75) G9(1.75,-0.75) G10(2.25,-0.75) H1(-2.25,-1.25) H2(-1.75,-1.25) H3(-1.25,-1.25) H4(-0.75,-1.25) H5(-0.25,-1.25) H6(0.25,-1.25) H7(0.75,-1.25) H8(1.25,-1.25) H9(1.75,-1.25) H10(2.25,-1.25) J1(-2.25,-1.75) J2(-1.75,-1.75) J3(-1.25,-1.75) J4(-0.75,-1.75) J5(-0.25,-1.75) J6(0.25,-1.75) J7(0.75,-1.75) J8(1.25,-1.75) J9(1.75,-1.75) J10(2.25,-1.75) K1(-2.25,-2.25) K2(-1.75,-2.25) K3(-1.25,-2.25) K4(-0.75,-2.25) K5(-0.25,-2.25) K6(0.25,-2.25) K7(0.75,-2.25) K8(1.25,-2.25) K9(1.75,-2.25) K10(2.25,-2.25)
CAP2-5_3-33X13H13
  rect 1.5x1.5 hole 1.016: 1(-2.65,0) 2(2.65,0)
CMC4-0_87X0_67H0_5
  rect 0.3x0.3 smd: 1(-0.25,-0.25) 2(0.25,-0.25) 3(0.25,0.25) 4(-0.25,0.25)
CRY4-1_6X1_2H0_65
  custom 0.138x0.138 smd: 1(-0.575,-0.425) 2(0.575,-0.425) 3(0.575,0.425) 4(-0.575,0.425)
CRY4-2016
  rect 0.75x0.7 smd: 1(-0.675,-0.5) 2(0.675,-0.5) 3(0.675,0.5) 4(-0.675,0.5)
DFN8-0_4-1_6X1_2H0_4-P
  rect 0.21x0.4 smd: 1(-0.6,-0.55) 2(-0.2,-0.55) 3(0.2,-0.55) 4(0.6,-0.55) 5(0.6,0.55) 6(0.2,0.55) 7(-0.2,0.55) 8(-0.6,0.55)
  rect 1.3x0.3 smd: 9(0,0)
DFN1006-2L-H0_5
  rect 0.55x0.6 smd: 1(-0.425,0) 2(0.425,0)
DFN1212-4-SQ1_2H0_4
  custom 0.09x0.09 smd: 1(-0.51,-0.42) 2(0.51,-0.42) 3(0.51,0.42) 4(-0.51,0.42)
  custom 0.195x0.195 smd: 5(0,0)
DUP4-1X0_5H0_4
  rect 0.3x0.2 smd: 1(-0.25,-0.2) 2(0.25,-0.2) 3(0.25,0.2) 4(-0.25,0.2)
ESD0402H0_6
  rect 0.6x0.55 smd: 1(-0.55,0) 2(0.55,0)
F3418H0_7
  rect 1x1.6 smd: 1(-1.5,0) 2(1.5,0)
FB0402H0_5
  rect 0.5x0.5 smd: 1(-0.45,0) 2(0.45,0)
FB0603H0_8
  rect 0.914x0.762 smd: 1(-0.8,0) 2(0.8,0)
H4_0D1_9
  round 4 hole 1.9: 1(0,0)
HOLE4_0D2_4
  round 4 hole 2.4: 1(0,0)
LED0603X2H0_35
  rect 0.8x0.8 smd: 1(-0.75,0) 2(0.75,0)
MARK-TOP
  round 1.016 smd: 1(0,0)
NILE-PM8005-SHD
  rect 0.5x1.2 smd: 1(-4.15,5.7)
NILE-POWER-SHD
  rect 1.85x0.7 smd: 1(-4.2,16.04)
NILE-WIFI-SHD
  rect 1.85x0.7 smd: 1(2.2,6.7)
NSM0411DT-BL-H1_1
  rect 0.457x1.016 smd: 1(0.425,-0.675) 2(0.425,0.675) 3(-0.425,0.675) 4(-0.425,-0.675)
  rect 1.321x0.66 smd: 5(0,-1.875) 7(0,1.875)
  rect 0.66x2.388 smd: 6(1.375,0) 8(-1.375,0)
RAJ5-3_5X3_5H4
  round 1.4 hole 0.85: 1(-1.27,1.27) 2(1.27,1.27) 3(1.27,-1.27) 4(-1.27,-1.27) 5(0,0)
RF3-SQ2_6H1_25-UFL-R-SMT-1
  rect 1x1.05 smd: 1(0,-1.525)
  rect 1.05x2.2 smd: 2(-1.475,0) 3(1.475,0)
RF4-MM8030H1
  rect 0.5x0.4 smd: 1(0,0.95) 2(0,-0.95)
  custom 0.175x0.175 smd: 3(-0.8,0) 4(0.8,0)
RF6-0_35-SQ1_0H1_0
  rect 0.4x0.2 smd: 1(-0.485,0.35) 3(-0.485,-0.35) 4(0.485,-0.35) 5(0.485,0) 6(0.485,0.35)
  custom 0.195x0.195 smd: 2(0,0)
SAW5-1_35X1_05H0_5
  rect 0.425x0.325 smd: 1(-0.588,0) 3(0.588,-0.288) 4(0.588,0.288)
  rect 0.25x0.525 smd: 2(0,-0.388) 5(0,0.388)
SC0201
  rect 0.35x0.35 smd: 1(-0.287,0) 2(0.287,0)
SC0402
  custom 0.129x0.129 smd: 1(-0.443,0) 2(0.443,0)
SC0603
  custom 0.138x0.138 smd: 1(-0.675,0) 2(0.675,0)
SC0603-CL10A226MP8NUNE
  custom 0.138x0.138 smd: 1(-0.725,0) 2(0.725,0)
SC0805
  rect 1x1.25 smd: 1(-0.95,0) 2(0.95,0)
SCP0_3
  rect 0.3x0.3 smd: 1(0,0) 2(0.3,0)
SCP0_15
  rect 0.15x0.15 smd: 1(0,0) 2(0.1,0)
SL0201H0_3
  rect 0.3x0.35 smd: 1(-0.312,0) 2(0.312,0)
SL2016-1_85H1_2
  rect 0.8x1.6 smd: 1(-0.925,0) 2(0.925,0)
SL3030-2_05H0_9
  rect 1.25x3.3 smd: 1(-1.025,0) 2(1.025,0)
SL3225H2_5
  rect 1.2x2 smd: 1(-1.6,0) 2(1.6,0)
SL4020-1_9H2
  rect 1.1x3.7 smd: 1(-1.51,-0.01) 2(1.49,-0.01)
SOD123H1_4
  rect 0.9x1.2 smd: 1(-1.829,0) 2(1.829,0)
SOT23-5H1_4
  oval 0.65x1.25 smd: 1(-0.95,-1.31) 2(0,-1.31) 3(0.95,-1.31) 4(0.95,1.31) 5(-0.95,1.31)
SOT23-6H1_4
  rect 0.6x1 smd: 1(-0.95,-1.2) 2(0,-1.2) 3(0.95,-1.2) 4(0.95,1.2) 5(0,1.2) 6(-0.95,1.2)
SOT23H1_1
  oval 0.55x0.9 smd: 1(-0.95,-1.15) 2(0.95,-1.15) 3(0,1.15)
SR0201
  rect 0.35x0.35 smd: 1(-0.287,0) 2(0.287,0)
SR0402
  custom 0.129x0.129 smd: 1(-0.443,0) 2(0.443,0)
SR0603
  custom 0.138x0.138 smd: 1(-0.675,0) 2(0.675,0)
SW4-4_85X3_55H1_25
  round 0.8 hole 0.8 unplated: (0,-0.9) (0,0.9)
  rect 1.4x0.9 smd: 1(-1.8,-0.65) 2(1.8,-0.65) 3(1.8,0.65) 4(-1.8,0.65)
TP0_5
  round 0.5 smd: 1(0,0)
TP0_6
  round 0.6 smd: 1(0,0)
TP0_9
  round 0.9 smd: 1(0,0)
TP1-5_9X2H3_7
  rect 3.4x2 smd: 1(-0.2,0)
TP1_0
  round 1 smd: 1(0,0)
TP2_0
  round 2 smd: 1(0,0)
unnamed#2
  round 1.55 hole 1.55 unplated: (0,0)
USB5-7_5X5_3H2_7
  rect 0.4x1.35 smd: 1(-1.3,-0.225) 2(-0.65,-0.225) 3(0,-0.225) 4(0.65,-0.225) 5(1.3,-0.225)
  oval 1.05x1.25 hole 0.65x0.85: 6(-2.45,0) 7(2.45,0)
  rect 2.1x1.9 hole 1.4x0.66: 8(-3.6,-2.9) 9(3.6,-2.9)
VQFN20-0_5-4_5X3_5H1_0
  rect 0.24x0.6 smd: 1(-0.775,2.15) 10(-0.775,-2.15) 11(0.775,-2.15) 20(0.775,2.15)
  rect 0.6x0.24 smd: 2(-1.65,1.75) 3(-1.65,1.25) 4(-1.65,0.75) 5(-1.65,0.25) 6(-1.65,-0.25) 7(-1.65,-0.75) 8(-1.65,-1.25) 9(-1.65,-1.75) 12(1.65,-1.75) 13(1.65,-1.25) 14(1.65,-0.75) 15(1.65,-0.25) 16(1.65,0.25) 17(1.65,0.75) 18(1.65,1.25) 19(1.65,1.75)
  custom 0.547x0.547 smd: 21(0,0)
VQFN48-0_5-7X7H1
  rect 0.7x0.28 smd: 1(-3.4,2.75) 2(-3.4,2.25) 3(-3.4,1.75) 4(-3.4,1.25) 5(-3.4,0.75) 6(-3.4,0.25) 7(-3.4,-0.25) 8(-3.4,-0.75) 9(-3.4,-1.25) 10(-3.4,-1.75) 11(-3.4,-2.25) 12(-3.4,-2.75) 25(3.4,-2.75) 26(3.4,-2.25) 27(3.4,-1.75) 28(3.4,-1.25) 29(3.4,-0.75) 30(3.4,-0.25) 31(3.4,0.25) 32(3.4,0.75) 33(3.4,1.25) 34(3.4,1.75) 35(3.4,2.25) 36(3.4,2.75)
  rect 0.28x0.7 smd: 13(-2.75,-3.4) 14(-2.25,-3.4) 15(-1.75,-3.4) 16(-1.25,-3.4) 17(-0.75,-3.4) 18(-0.25,-3.4) 19(0.25,-3.4) 20(0.75,-3.4) 21(1.25,-3.4) 22(1.75,-3.4) 23(2.25,-3.4) 24(2.75,-3.4) 37(2.75,3.4) 38(2.25,3.4) 39(1.75,3.4) 40(1.25,3.4) 41(0.75,3.4) 42(0.25,3.4) 43(-0.25,3.4) 44(-0.75,3.4) 45(-1.25,3.4) 46(-1.75,3.4) 47(-2.25,3.4) 48(-2.75,3.4)
  rect 4.08x4.08 smd: 49(0,0)

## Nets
GND: BTTN1.1(T1) BTTN1.2(T2) C9.2 C65.2 C115.2 C116.2 C118.2 C119.2 C122.2 C123.2 C124.2 C125.2 C126.2 C127.2 C128.2 C129.2 C131.2 C134.2 C138.2 C139.2 C142.2 C143.2 C144.2 C147.2 C148.2 C151.2 C152.2 C225.2 C226.2 C228.2 C229.2 C232.2 C255.2 C256.2 C257.2 C258.2 C259.2 C260.2 C261.2 C262.2 C263.2 C264.2 C265.2 C266.2 C267.2 C268.2 C269.2 C270.2 C271.2 C272.2 C273.2 C274.2 C275.2 C277.2 C278.1 C280.2 C281.2 C283.2 C285.2 C309.2 C310.2 C358.2 C359.1 C360.2 C361.2 C365.1 C366.2 C367.2 C369.1 C370.2 C371.2 C373.2 C374.1 C375.1 C376.2 C377.1 C378.2 C379.1 C380.2 C381.2 C383.2 C384.2 C394.2 C395.2 C416.2 C417.2 C418.2 C424.1 C437.1 C438.2 C446.2 C452.2 C453.2 C556.2 C4607.2 C4608.2 C6216.2 C6217.1 C6223.1 C6224.1 C6225.1 C6231.1 C6233.2 C6234.2 C6270.2 C6271.2 C6272.2 C6273.1 C6274.1 C6277.2(-) C6278.2 C6283.1 C6288.2 C6289.2 C6299.2 C6300.2 C6302.1 C6303.2 C6305.2 C6306.1 C6307.1 C6308.1 C6309.2 C6361.1 C6362.1 C6363.1 C6364.1 C6365.1 C6366.2 C6367.1 C6368.2 C6369.1 C6370.2 C6371.2 C6376.1 C6379.2 C6380.2 C6381.2 C6383.2 C6384.2 C6385.2 C6386.2 C6387.2 C6388.2 C6389.2 C6393.1 C6394.2 C6395.1 C6396.1 C6397.1 C6398.1 C6399.1 C6400.1 C6401.1 C6402.1 C6403.1 C6404.2 C6405.2 C6406.2 CN3.1(GND1) CON2.1(GND1) CON2.2(GND2) CON2.3(GND3) CON2.4(GND4) D31.2 D32.2 D33.2 D37.2 D38.2 D39.2 D48.2 D3829.2 D3845.2 D3847.2 D3848.2 D3865.2 FL1.1(GND) FL2.2(GND1) FL2.3(GND2) FL2.5(GND3) G15.1(G) G16.1(G) G17.1(G) G18.1(G) HOLE1.1(TP) HOLE3.1(TP) J3.3(G1) J3.4(G2) J4.2(GND1) J4.3(GND2) L20.1 L22.1 L25.1 L26.1 L27.2 L28.2 L29.1 L3704.1 L3711.1 L3713.1 L3715.1 Q8.2(SOURCE) Q2711.2(SOURCE) Q2712.2(SOURCE) R7.2 R61.1 R88.2 R89.1 R106.2 R117.2 R118.2 R124.2 R147.2 R198.2 R199.2 R200.2 R201.2 R231.1 R413.2 R4647.2 R4648.2 R6537.1 R6547.1 R6579.1 R6580.2 R6627.1 R6631.2 R6632.1 R6655.1 R6657.1 R6673.1 R6681.1 R6682.1 R6688.2 SH2.1 SH3.1 SH5.1 TP71.1(TP) TP83.1(TP) U2.3(LCON) U2.5(GND) U2.9(EPAD_GND) U11.6(TEST_EN_VPP) U11.17(REF_GND) U11.22(GND_WLP_TST) U11.23(CMN_GND_9) U11.24(CMN_GND_10) U11.25(CMN_GND_11) U11.26(CMN_GND_12) U11.27(CMN_GND_13) U11.32(CMN_GND_14) U11.36(CMN_GND_1) U11.37(CMN_GND_2) U11.43(CMN_GND_3) U11.45(CMN_GND_4) U11.46(CMN_GND_5) U11.47(CMN_GND_6) U11.48(CMN_GND_7) U11.49(CMN_GND_8) U18.1(GND_SEALRING2) U18.6(GND_FM_RXFE) U18.7(FM_RX_HEADSET) U18.13(GP_OUT) U18.18(GND_BT_FM_BBPLL_A) U18.19(GND_BT_SYNTH) U18.20(GND_FM_VCO) U18.21(GND_GP) U18.24(GND_ISO) U18.28(GND_PDET) U18.30(GND_DIG) U18.33(GND_BT_BB) U18.35(GND_WL_BT_RXFE_CH0) U18.38(GND_XTAL) U18.40(GP_EN) U18.41(GND_DPD_CH0) U18.47(GND_ESD_0) U18.48(GND_WL_BT_DRV_CH0) U18.49(GND_IO) U18.51(GND_WL_SYNTH_CH0) U18.54(GND_WL_2G_PA_CH0) U18.62(GND_WL_BALUN_CH0) U18.65(GND_PM) U18.66(GND_WL_BB_CH0) U18.67(GND_WL_5G_PA_CH0) U18.74(GND_WL_5G_DRV_CH0) U18.78(GND_SEALRING3) U18.81(GND_WL_5G_RXFE_CH0) U18.82(GND_SEALRING1) U19.5(GND) U19.9(PAD) U22.2(GND) U33.44(RES) U33.46(VDD_SEL) U33.49(GND) U35.5(GND1) U35.6(GND2) U35.7(GND3) U35.8(GND4) U3702.2(GND) U3704.2(GND) U3708.5(GND) U4619.2(GND) U6834.11(NC1) U6834.12(NC2) U6834.20(AGND) U6834.21(PGND) U6838.B5(GND_1) U6838.C6(GND_2) U6838.D5(GND_3) U6838.D7(GND_4) U6838.D9(GND_5) U6838.E9(GND_6) U6838.F2(GND_7) U6838.G9(GND_8) U6838.H6(GND_9) U6838.J1(GND_10) U6838.J3(GND_11) U6838.J9(GND_12) USB1.5(G) USB1.6(S1) USB1.7(S2) USB1.8(S3) USB1.9(S4) Y1.2(GND) Y1.4(SENSOR) Y2.2(GND1) Y2.4(GND2)
V5P0_HUB: C4607.1 R6672.1 R6678.1 U3702.1(OUT)
VBAT_EX: C418.1 C6216.1 C6217.2 C6234.1 C6274.2 C6361.2 C6362.2 C6363.2 C6364.2 C6368.1 C6369.2 R6362.1 R6656.1 R6658.2 R6685.2 U2.7(VDD1) U2.8(VDD2) U3708.2(BIAS) U3708.4(VIN)
VBATT: D3853.2(C) Q2710.2(SOURCE)
VBUS2_OUT_5V_EN: R147.1 U3704.4(EN)
VBUS_OUT_5V: D37.1 D3600.2(C) TP68.1(TP) USB1.1(V)
VDD11D_PM: C273.1 U18.43(VDD11D_PM)
VDD13_BT: C258.1 C259.1 C260.1 C264.1 C265.1 C268.1 C271.1 R100.2 U18.4(VDD13_BT_FM_BBPLL) U18.5(VDD13_BT_SYNTH) U18.12(VDD13_FM) U18.26(VDD13_BT_BB_WL) U18.29(VDD13_PM) U18.46(VDD13_WL_SYNTH_CH0)
VDD33_FEM: C255.1 C256.1 C257.1 C261.1 C266.1 C270.1 C272.1 R102.2 U18.2(VDD33_FEM) U18.34(VDD33_WL_BT_DRV_CH0) U18.55(VDD33_WL_CH0) U18.61(VDD33_WL_5G_DRV_CH0) U18.71(VDD33_PM_DLDO)
VDD_CAP: C6270.1 C6300.1 L3703.1 L3709.1 R6285.1 R6578.1 U4619.6(VBAT)
VDDIO_954_EN: R7.1 U2.6(CE)
VIN_8V5: B34.1 C438.1 C6406.1 TP107.1(TP)
ANT_2G_CH0: C288.2 FL1.3(2.4G) L29.2
BB_PLL_REF_CLK: R115.2
BIST_954: R200.1 U33.6(BISTEN)
BT_FM_SB_CLK: U18.22(SB_CLK)
BT_FM_SB_DATA: U18.63(SB_DATA)
CAM2_VDD: B2.2 B3.2 C115.1 C116.1 R20.2 R21.2 R195.1 R196.1 U2.1(VOUT1) U2.2(VOUT2) U2.4(VFB)
CAM_MCLK2: R194.1
CCI_I2C_SCL1: R21.1 U33.2(SCL)
CCI_I2C_SDA1: R20.1 U33.1(SDA)
DC_IN: C6271.1 Q2710.1(GATE) R6579.2
FAULT_N: U11.16(FAULT_N)
IDX_954: R199.1 U33.35(IDX)
KEY_VOLP_N: D3845.1 R286.1 U11.60(GPIO_02)
LED_EN: Q2711.1(GATE)
LNA_EN_5G_CH0: C281.1 U18.39(WL_BT_FEM_1) U22.6(VCTL1)
LPI_UART_1_RX: U18.3(SENS_TXD)
LPI_UART_1_TX: U18.23(SENS_RXD)
MIPI_CSI1_CLK_M: F2820.1(I|O1)
MIPI_CSI1_CLK_M_R: F2820.4(I|O4) U33.11(CSI_CLK0N)
MIPI_CSI1_CLK_P: F2820.2(I|O2)
MIPI_CSI1_CLK_P_R: F2820.3(I|O3) U33.12(CSI_CLK0P)
MIPI_CSI1_L0_DATA_M: F2822.1(I|O1)
MIPI_CSI1_L0_DATA_M_R: F2822.4(I|O4) U33.13(CSI_D0N)
MIPI_CSI1_L0_DATA_P: F2822.2(I|O2)
MIPI_CSI1_L0_DATA_P_R: F2822.3(I|O3) U33.14(CSI_D0P)
MIPI_CSI1_L1_DATA_M: F2818.1(I|O1)
MIPI_CSI1_L1_DATA_M_R: F2818.4(I|O4) U33.15(CSI_D1N)
MIPI_CSI1_L1_DATA_P: F2818.2(I|O2)
MIPI_CSI1_L1_DATA_P_R: F2818.3(I|O3) U33.16(CSI_D1P)
MIPI_CSI1_L2_DATA_M: F2821.1(I|O1)
MIPI_CSI1_L2_DATA_M_R: F2821.4(I|O4) U33.21(CSI_D2N)
MIPI_CSI1_L2_DATA_P: F2821.2(I|O2)
MIPI_CSI1_L2_DATA_P_R: F2821.3(I|O3) U33.22(CSI_D2P)
MIPI_CSI1_L3_DATA_M: F2819.1(I|O1)
MIPI_CSI1_L3_DATA_M_R: F2819.4(I|O4) U33.23(CSI_D3N)
MIPI_CSI1_L3_DATA_P: F2819.2(I|O2)
MIPI_CSI1_L3_DATA_P_R: F2819.3(I|O3) U33.24(CSI_D3P)
MIPI_DSI0_CLK_M: F2824.3(I|O3)
MIPI_DSI0_CLK_P: F2824.4(I|O4)
MOD_AP_READY: TP100.1(TP)
MOD_POWER_ON: Q8.1(GATE) R6537.2
MOD_POWER_ON_R: Q8.3(DRAIN) R6658.1
MOD_RESET: Q2712.1(GATE) R6655.2
MOD_RESET_R: C437.2 Q2712.3(DRAIN) R6656.2
MOD_RI: R6536.2
MOD_V_BACK: C6366.1
MOD_VINT: C6365.2 R6663.1
MOD_W_DISABLE: TP101.1(TP)
MODE_954: R196.2 R198.1 U33.37(MODE)
MSS_LTE_COEX_RX: U18.70(COEX_TXD)
MSS_LTE_COEX_TX: U18.57(COEX_RXD)
PA_EN_5G_CH0: C283.1 U18.58(WL_BT_FEM_5) U22.4(VCTL2)
PDB_954: C358.1 R195.2 U33.30(PDB)
PM_RESIN_N: D3847.1 R284.1
PON_OUT: U11.33(PON_1)
QCS_GPIO_76: U33.28(GPIO0)
QCS_GPIO_77: U33.27(GPIO1)
QCS_GPIO_78: U33.26(GPIO2)
QCS_GPIO_91: D3848.1 R289.1
QCS_GPIO_92: D3829.1 R288.1
QUP6_HCI_UART_CTS_N: U18.50(RTS)
QUP6_HCI_UART_RFR_N: U18.64(CTS)
QUP6_HCI_UART_RX: U18.8(TXD)
QUP6_HCI_UART_TX: R253.2 U18.16(RXD)
RIN0_M: C364.2 R6547.2
RIN0_P: B9.2 C363.2 CON2.5 D48.1 R201.1
SDM_DMIC_CLK2: D33.1 U35.3(CLK)
SDM_DMIC_DATA2: D32.1 U35.4(DAT)
SLB: U11.66(GPIO_03)
SLEEP_CLK: R110.1
SPMI_CLK: U11.50(SPMI_CLK)
SPMI_DATA: U11.55(SPMI_DATA)
UIM_CLK_R: TP82.1(TP)
UIM_DATA_R: TP80.1(TP)
UIM_DETECT_F: R6663.2 TP78.1(TP)
UIM_PWR_R: C6367.2 TP79.1(TP)
UIM_RESET_R: TP81.1(TP)
USB2_HS_D_M: U6838.A8(US_DM)
USB2_HS_D_P: U6838.A9(US_DP)
USB_HUB1_DN: R6654.1 U6838.C8(DS1_DM)
USB_HUB1_DP: R6653.1 U6838.C7(DS1_DP)
USB_HUB2_DN: D38.1 TP69.1(TP) U6838.A5(DS2_DM) USB1.2(D-)
USB_HUB2_DP: D39.1 TP70.1(TP) U6838.A6(DS2_DP) USB1.3(D+)
USB_HUB_PW_EN: R4647.1 U3702.4(EN)
USB_HUB_RST_R: R479.1 U6838.F7(RESETN)
USB_VDD33: B32.1
V_LEDA: C6283.2 PS3.2
VPH_PWR: C221.1 C223.1 C224.1 C227.1 C230.1 C231.1 C274.1 R87.1 U11.1(VDD_S1_1) U11.3(VDD_S4_1) U11.7(VDD_S1_2) U11.9(VDD_S4_2) U11.12(VDD_S1_3) U11.14(VDD_S4_3) U11.38(VPH_PWR) U11.44(VBOB) U11.56(VDD_S2_1) U11.58(VDD_S3_1) U11.62(VDD_S2_2) U11.64(VDD_S3_2) U11.67(VDD_S2_3) U11.69(VDD_S3_3) U19.3(LCON) U19.7(VIN2) U19.8(VIN1)
VREG_5V: C309.1 C4608.1 U3702.5(IN) U3704.5(IN)
VREG_HUB_1P2: B30.1 C6231.2 C6278.1 C6371.1 C6379.1 C6380.1 C6381.1 C6383.1 C6384.1 C6385.1 C6386.1 C6387.1 C6388.1 C6389.1 U3708.1(VOUT) U6838.A10(AVDD12_1) U6838.C9(AVDD12_2) U6838.F9(AVDD12_3) U6838.H1(AVDD12_4) U6838.H10(AVDD12_5) U6838.J2(AVDD12_6)
VREG_HUB_3P3: B32.2 B33.1 C424.2 C6223.2 C6224.2 C6225.2 C6370.1 R479.2 R6676.2 R6679.1 R6680.1 R6683.1 R6684.1 R6686.2 R6687.2 R6689.2 R6690.2 U6838.A7(AVDD33_2) U6838.B4(VDD_IO_1) U6838.B6(AVDD33_3) U6838.E7(VDD_IO_2) U6838.F3(AVDD33_4) U6838.G6(VDD_IO_3)
VREG_L3A_1P3: R100.1
VREG_L8A_1P8: C126.1 C127.1 C128.1 C129.1
VREG_L9A_1P8: C267.1 C269.1 U18.32(VDD18_XTAL) U19.6(CE)
VREG_L13A_1P8: B4.2 C9.1 C65.1 C122.1 C123.1 C262.1 C263.1 R253.1 R6671.1 U11.5(VDD_MSM_IO) U18.56(VDD18_IO)
VREG_L19A_3P0: C119.1 C124.1 C125.1
VREG_S1C_S4C_0P752: C232.1 L8.2 L11.2
VREG_S2C_1P125: C134.1 C142.1 C143.1 C147.1 C148.1 C151.1 C152.1 C225.1 L9.2 R60.1
VREG_S3A_0P6: C131.1 C138.1 C139.1 C144.1 R4656.1 R4657.1
VREG_S3C_0P752: C228.1 L10.2
VREG_WL_3P3: C275.1 R102.1 U19.1(VOUT1) U19.2(VOUT2) U19.4(SENSE)
VSNS_CX_M: U11.31(VREF_NEG_S4) U11.35(VREF_NEG_S1)
VSNS_CX_P: U11.29(VREG_S1) U11.30(VREG_S4)
VSNS_DDR_VDD2_M: R61.2 U11.40(VREF_NEG_S2)
VSNS_DDR_VDD2_P: R60.2 U11.34(VREG_S2)
VSNS_GFX_M: U11.42(VREF_NEG_S3)
VSNS_GFX_P: U11.41(VREG_S3)
WCN_RFCLK1: C442.1
WCSS_CH0_CMD_CLK: U18.9(WL_CMD_CLK_CH0)
WCSS_CH0_CMD_DATA: R105.2
WL_BT_COEX_CLK: U18.76(COEX_CLK)
WL_BT_COEX_DATA: U18.77(COEX_DATA)
WL_BT_RFIO_2G_CH0: C287.1 L26.2 U18.42(WL_RF_RFIO_2G_CH0)
WL_CH0_BB_I_M: C6289.1 U18.73(WL_BB_IN_TX)
WL_CH0_BB_I_P: C6288.1 U18.80(WL_BB_IP_TX)
WL_CH0_BB_Q_M: U18.72(WL_BB_QN_TX)
WL_CH0_BB_Q_P: U18.79(WL_BB_QP_TX)
WL_CH1_BB_I_M: U18.60(WL_BB_IN_RX)
WL_CH1_BB_I_P: U18.53(WL_BB_IP_RX)
WL_CH1_BB_Q_M: U18.59(WL_BB_QN_RX)
WL_CH1_BB_Q_P: U18.52(WL_BB_QP_RX)
WL_RFI_5G_CH0: R119.2 U18.75(WL_RFI_5G_CH0)
WL_RFO_5G_CH0: R116.2 R118.1 U18.68(WL_RFO_5G_CH0)
WLAN_SW_CTRL: U18.15(SW_CTRL)
N13749854: C226.1 U11.11(REF_BYP)
N13749894: C229.1 U11.39(AVDD_BYP)
N13749950: R87.2 R88.1 U11.71(GPIO_04)
N13750348: C221.2 G15.2(S) U11.8(GND_S1_1) U11.19(GND_S1_2)
N13750434: C223.2 C224.2 G16.2(S) U11.52(GND_S2_1) U11.63(GND_S2_2)
N13750548: C227.2 G18.2(S) U11.54(GND_S3_1) U11.65(GND_S3_2)
N13750620: C230.2 C231.2 G17.2(S) U11.10(GND_S4_1) U11.21(GND_S4_2)
N13750716: L8.1 U11.2(VSW_S1_1) U11.13(VSW_S1_2) U11.18(VSW_S1_3)
N13750828: L9.1 U11.51(VSW_S2_1) U11.57(VSW_S2_2) U11.68(VSW_S2_3)
N13750950: L10.1 U11.53(VSW_S3_1) U11.59(VSW_S3_2) U11.70(VSW_S3_3)
N13751070: L11.1 U11.4(VSW_S4_1) U11.15(VSW_S4_2) U11.20(VSW_S4_3)
N13751276: R89.2 U11.28(SYS_CLK_IN)
N13764432: R110.2 U18.36(LF_CLK_IN)
N13764562: C278.2 C442.2 U18.44(XTALI) Y1.3(XTAL-)
N13764570: C277.1 U18.37(XTALO) Y1.1(XTAL+)
N13764650: C279.1 U18.69(CLK_OUT)
N13764670: C279.2 C280.1 R115.1
N13764744: R105.1 U18.17(WL_CMD_DATA_CH0)
N13765314: R106.1 U18.10(WP_IP)
N13765772: C6329.2 U22.5(INPUT)
N13765776: C286.1 C6329.1 L3704.2
N13765780: C282.1 U22.1(OUTPUT1)
N13765784: C282.2 R116.1 R117.1
N13765868: C284.2 C285.1 R119.1
N13766128: C286.2 FL1.4(5G) L25.2
N13766140: FL1.2(ANT) R121.1
N13766428: C284.1 U22.3(OUTPUT2)
N13766504: C556.1 R120.1 R121.2
N13766548: C288.1 FL2.4(ANT) L28.1
N13766584: C287.2 FL2.1(RX_TX) L27.1
N13766616: J3.1(IN) R120.2
N13766620: J3.2(OUT) L20.2 R122.1
N13766628: D3865.1 J4.1(A) L22.2 R122.2
N13778471: C446.1 D3707.2(C) PS3.1
N13780185: L3710.1 R286.2
N13780193: BTTN3.1(T1) BTTN3.2(T2) L3711.2
N13780517: D3707.1(A)
N13780603: L3712.1 R284.2
N13780655: BTTN5.1(T1) BTTN5.2(T2) L3713.2
N13781083: BTTN1.3(T3) BTTN1.4(T4) R288.2
N13781141: BTTN6.1(T1) BTTN6.2(T2) L3715.2
N13781157: BTTN6.3(T3) BTTN6.4(T4) L3714.2
N13781221: L3714.1 R289.2
N13788470: R4648.1 U3702.3(ISET)
N13792202: C310.1 D3600.1(A) U3704.1(OUT)
N13792228: R413.1 U3704.3(ISET)
N13800559: C377.2 C378.1 U33.3(VDD11_D)
N13800591: C363.1 U33.41(RIN0+)
N13800619: C364.1 U33.42(RIN0-)
N13800787: C379.2 C380.1 U33.20(VDD11_CSI)
N13800859: TP25.1(TP) U33.4(XOUT)
N13800863: R194.2 U33.5(XIN/REFCLK)
N13800897: C374.2 C376.1 U33.34(VDD11_FPD1)
N13800911: C373.1 C375.2 U33.43(VDD11_FPD0)
N13800959: R6548.2 U33.33(RIN1-)
N13800993: R6548.1 U33.32(RIN1+)
N13800997: C113.1 U33.38(CMLOUTP)
N13801001: C114.1 U33.39(CMLOUTN)
N13801143: B3.1 C381.1 C383.1 C384.1 C453.1 U33.7(VDDIO) U33.29(VDDIO_1)
N13801371: B2.1 C359.2 C360.1 C361.1 C365.2 C366.1 C367.1 C369.2 C370.1 C371.1 U33.17(VDD18_CSI) U33.31(VDD18_FPD1) U33.36(VDD18_P1) U33.40(VDD18_FPD0) U33.45(VDD18_P0)
N13801403: TP27.1(TP) U33.48(LOCK)
N13801411: TP26.1(TP) U33.47(PASS)
N13802455: B34.2 C6233.1 C6405.1 L36.1 R6546.1
N13802681: B35.1 L36.2 R6546.2
N13806908: R231.2 U35.2(L/R)
N13806920: B4.1 C394.1 C395.1 C6273.2 D31.1 U35.1(VDD)
N14025873: BTTN5.3(T3) BTTN5.4(T4) L3712.2
N14050811: BTTN3.3(T3) BTTN3.4(T4) L3710.2
N14316805: LED4400.2(C) Q2711.3(DRAIN)
N14502607: C6277.1(+) R6285.2
N14734601: F2824.2(I|O2)
N14734631: F2824.1(I|O1)
N15879819: L3703.2 U4619.1(SW)
N15880146: C6272.1 C6299.1 R6581.1 R6642.1 U4619.5(VOUT) U6834.9(VIN)
N15881033: R6580.1 R6581.2 U4619.4(FB)
N15881893: R6578.2 U4619.3(EN)
N15883520: C6301.2 L3709.2 R6628.1 R6634.1 R6635.1 U6834.4(SW1) U6834.5(SW2) U6834.6(SW3) U6834.7(SW4)
N15883653: C6301.1 U6834.8(BOOT)
N15883704: C6302.2 R6626.1 U6834.1(VCC)
N15884895: R6626.2 R6642.2 U6834.2(EN)
N15885073: R6627.2 U6834.13(MODE)
N15887049: R6628.2 U6834.3(FSW)
N15888229: C6303.1 C6305.1 D3853.1(A) Q2710.3(DRAIN) R6636.1 U6834.14(VOUT1) U6834.15(VOUT2) U6834.16(VOUT3)
N15889567: C6310.2 R6630.2 R6631.1 U6834.17(FB)
N15892910: C6306.2 U6834.10(SS)
N15893880: R6632.2 U6834.19(ILIM)
N15895046: C6307.2 R6633.1
N15896834: C6308.2 R6633.2 U6834.18(COMP)
N15911517: C6309.1 R6634.2 R6635.2
N15911869: C6310.1 R6630.1 R6636.2
N16075101: R124.1 U18.27(WL_RF_PDET_IN_CH0)
N16803003: C118.1
N16803691: R4656.2
N16803695: R4657.2
N17038564: R6654.2
N17038587: R6653.2
N17045642: TP97.1(TP)
N17046059: TP98.1(TP)
N17057745: R6657.2
N17108422: TP102.1(TP)
N17108433: TP103.1(TP)
N17108458: TP104.1(TP)
N17108467: TP105.1(TP)
N17108508: R6536.1
N17215166: C416.1 U6838.E6(XTL_OUT) Y2.3(I)
N17215182: C417.1 U6838.E5(XTL_IN) Y2.1(O)
N17221264: R6671.2 R6685.1 U3708.3(EN)
N17222220: B30.2 C452.1 C6393.2 C6394.1 C6395.2 C6396.2 C6397.2 C6398.2 C6399.2 C6400.2 C6401.2 C6402.2 C6403.2 U6838.B10(DVDD12_1) U6838.D4(DVDD12_2) U6838.D6(DVDD12_3) U6838.D8(DVDD12_4) U6838.E1(DVDD12_5) U6838.E10(DVDD12_6) U6838.F5(DVDD12_7) U6838.H3(VDD_EFUSE) U6838.K3(DVDD12_8) U6838.K9(DVDD12_9)
N17233104: R6672.2 R6673.2 U6838.H2(VBUS _US)
N17251830: R6679.2 U6838.G5(MODE_SEL[0])
N17251848: R6680.2 U6838.F4(MODE_SEL[1])
N17253194: R6682.2 U6838.H5(RREF_SS)
N17253197: R6681.2 U6838.E2(RREF_USB2)
N17253674: R6683.2 U6838.G4(RESERVED1)
N17253745: TP106.1(TP) U6838.G3(SUSPEND)
N17256163: R6684.2 U6838.K6(US_OVRCURR)
N17264893: B33.2 C6376.2 C6404.1 U6838.A4(AVDD33_1)
N17436018: R6678.2 U6838.G2(VBUS _DS)
N17436514: R6686.1 U6838.H4(DS4_LED_SS)
N17437459: R6676.1 U6838.F6(DS4_OVRCURR)
N17438882: R6687.1 U6838.J8(DS1_OVRCURR)
N17439003: R6688.1 U6838.B9(DS3_LED_SS)
N17439463: R6689.1 U6838.B1(DS2_OVRCURR)
N17439531: R6690.1 U6838.B7(DS3_OVRCURR)
N17698423: B9.1 B35.2
N17709894: C113.2 R1.1 TP2.1(TP)
N17709914: C114.2 R1.2 TP6.1(TP)
N143167610: LED4400.1(A) R6362.2

Pads without a net: MK1 1; MK4 1; U11 61 72; U18 11 14 25 31 45; U33 8 9 10 18 19 25; U6838 A1 A2 A3 B2 B3 B8 C1 C2 C3 C4 C5 C10 D1 D2 D3 D10 E3 E4 E8 F1 F8 F10 G1 G7 G8 G10 H7 H8 H9 J4 J5 J6 J7 J10 K1 K2 K4 K5 K7 K8 K10; USB1 4

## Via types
v1: diameter 0.25, hole 0.1, INNER LAYER 9 to BOTTOM, 1493 vias
v2: diameter 0.25, hole 0.1, INNER LAYER 8 to INNER LAYER 9, 1186 vias
v3: diameter 0.381, hole 0.2, INNER LAYER 3 to INNER LAYER 8, 329 vias
v4: diameter 0.203, hole 0.076, INNER LAYER 9 to BOTTOM, 73 vias
v5: diameter 0.25, hole 0.1, TOP to INNER LAYER 2, 577 vias
v6: diameter 0.25, hole 0.1, INNER LAYER 2 to INNER LAYER 3, 306 vias
v7: diameter 0.381, hole 0.203, INNER LAYER 3 to INNER LAYER 8, 482 vias
v8: diameter 0.203, hole 0.076, INNER LAYER 8 to BOTTOM, 256 vias
